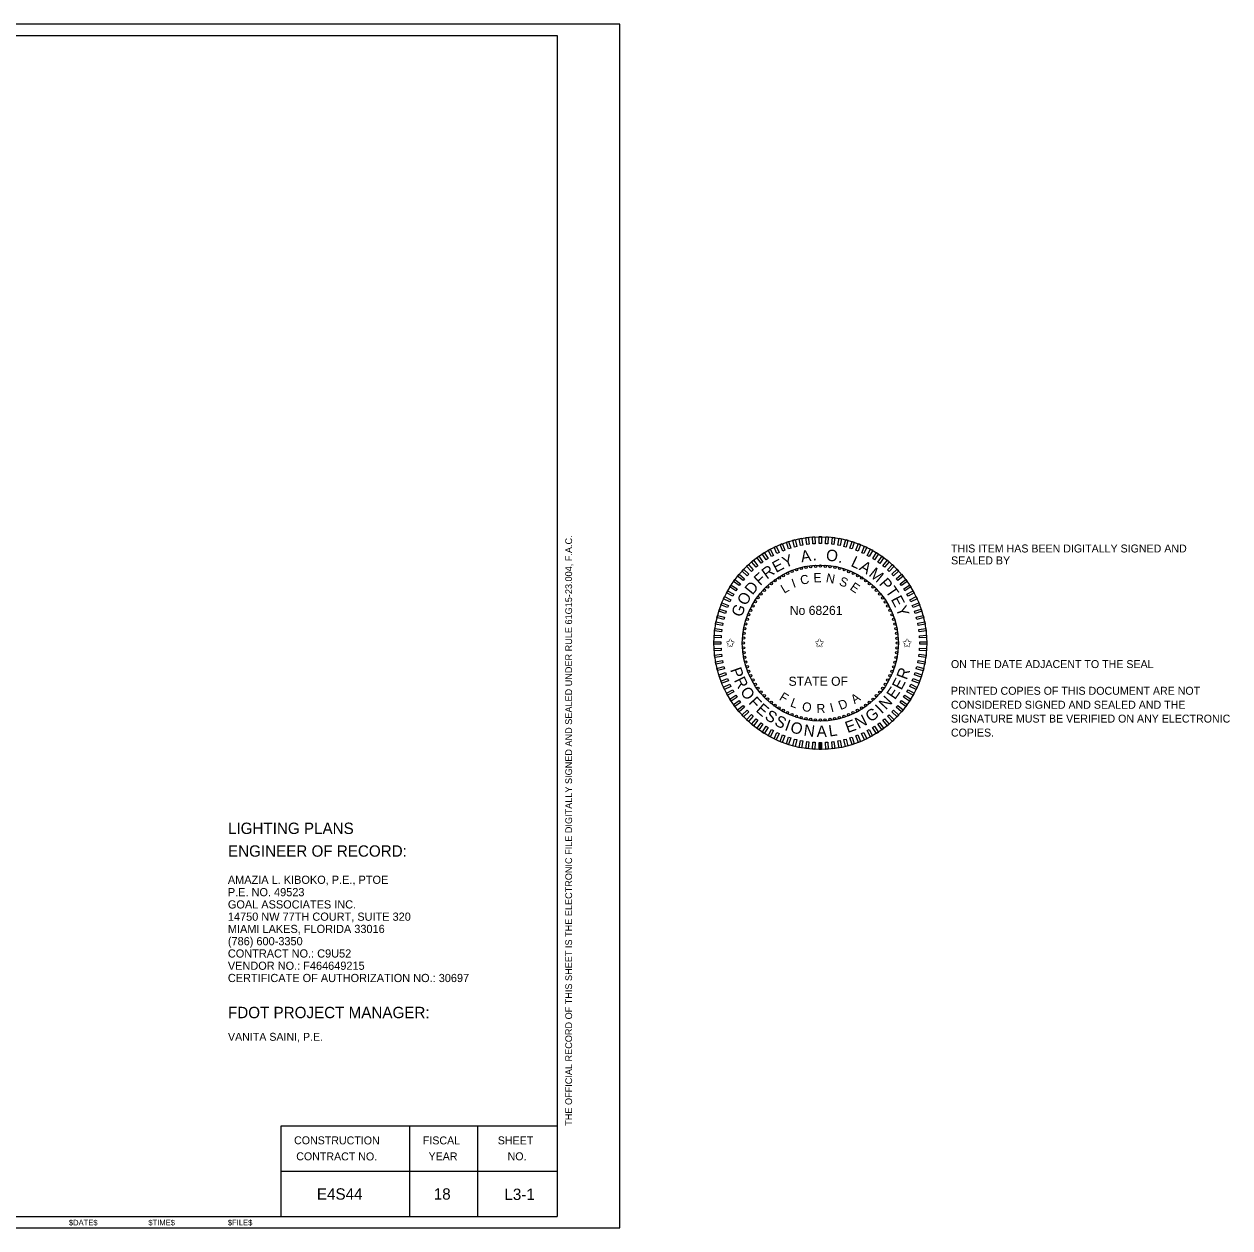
# Model space of a CAD drawing. Extents: x -820.2 to -798.4, y -2199.1 to -2188.5.
# Drawn here: x -808.97 to -798.35, y -2199.12 to -2188.52 of the extents above; entities that cross this region are included whole.
import ezdxf

# ---------------------------------------------------------------- set-up
doc = ezdxf.new("R2010")
doc.units = 0
for name, color, linetype in [('ActivePointCell_dp', 7, 'Continuous'), ('AdhocPoint_dp', 7, 'Continuous'), ('Logo_dp', 7, 'Continuous'), ('NonPlottingEle_dp', 7, 'Continuous'), ('PlotBorder_dp', 7, 'Continuous'), ('SheetBorder_dp', 7, 'Continuous'), ('SheetLines_dp', 7, 'Continuous'), ('TextLabel', 7, 'Continuous'), ('TextMinor', 7, 'Continuous'), ('TextMisc', 7, 'Continuous'), ('TextNotes', 7, 'Continuous'), ('TextShtNo', 7, 'Continuous')]:
    doc.layers.add(name, color=color, linetype=linetype)

msp = doc.modelspace()

# ---------------------------------------------------------------- linework, layer by layer
at = {"layer": 'ActivePointCell_dp'}
msp.add_line((-804.277, -2188.624), (-804.277, -2188.624), dxfattribs=at)
at = {"layer": 'AdhocPoint_dp'}
msp.add_line((-803.727, -2199.124), (-803.727, -2199.124), dxfattribs=at)
at = {"layer": 'Logo_dp'}
for p, q in [((-801.971, -2194.911), (-801.971, -2194.849)), ((-801.961, -2194.911), (-801.961, -2194.849)), ((-801.951, -2194.911), (-801.951, -2194.848))]:
    msp.add_line(p, q, dxfattribs=at)
for points in [[(-802.06, -2193.104), (-802.081, -2193.107), (-802.088, -2193.045), (-802.068, -2193.042)], [(-802.006, -2193.1), (-802.026, -2193.101), (-802.03, -2193.039), (-802.01, -2193.037)], [(-801.951, -2193.098), (-801.971, -2193.098), (-801.971, -2193.036), (-801.951, -2193.036)], [(-801.896, -2193.101), (-801.916, -2193.1), (-801.912, -2193.037), (-801.892, -2193.039)], [(-801.841, -2193.107), (-801.861, -2193.104), (-801.853, -2193.042), (-801.833, -2193.045)], [(-802.374, -2193.202), (-802.391, -2193.212), (-802.421, -2193.157), (-802.404, -2193.147)], [(-802.324, -2193.177), (-802.343, -2193.186), (-802.369, -2193.13), (-802.351, -2193.121)], [(-802.274, -2193.156), (-802.292, -2193.164), (-802.315, -2193.106), (-802.297, -2193.098)], [(-802.222, -2193.138), (-802.241, -2193.144), (-802.26, -2193.085), (-802.241, -2193.079)], [(-802.169, -2193.123), (-802.188, -2193.128), (-802.204, -2193.068), (-802.184, -2193.063)], [(-802.115, -2193.112), (-802.135, -2193.116), (-802.146, -2193.055), (-802.127, -2193.051)], [(-801.787, -2193.116), (-801.807, -2193.112), (-801.795, -2193.051), (-801.775, -2193.055)], [(-801.733, -2193.129), (-801.753, -2193.124), (-801.737, -2193.063), (-801.718, -2193.068)], [(-801.681, -2193.144), (-801.7, -2193.138), (-801.681, -2193.079), (-801.662, -2193.085)], [(-801.629, -2193.164), (-801.648, -2193.156), (-801.625, -2193.098), (-801.606, -2193.106)], [(-801.579, -2193.186), (-801.597, -2193.178), (-801.571, -2193.121), (-801.553, -2193.13)], [(-801.53, -2193.212), (-801.548, -2193.202), (-801.518, -2193.147), (-801.5, -2193.157)], [(-802.511, -2193.293), (-802.526, -2193.306), (-802.566, -2193.258), (-802.551, -2193.245)], [(-802.467, -2193.26), (-802.483, -2193.271), (-802.52, -2193.221), (-802.504, -2193.209)], [(-802.421, -2193.229), (-802.438, -2193.24), (-802.472, -2193.187), (-802.455, -2193.177)], [(-801.483, -2193.24), (-801.5, -2193.229), (-801.467, -2193.177), (-801.45, -2193.187)], [(-801.438, -2193.272), (-801.455, -2193.26), (-801.418, -2193.209), (-801.402, -2193.221)], [(-801.395, -2193.306), (-801.411, -2193.293), (-801.371, -2193.245), (-801.356, -2193.258)], [(-802.592, -2193.367), (-802.606, -2193.382), (-802.651, -2193.339), (-802.637, -2193.324)], [(-802.552, -2193.329), (-802.567, -2193.343), (-802.61, -2193.297), (-802.595, -2193.283)], [(-801.354, -2193.343), (-801.369, -2193.329), (-801.326, -2193.283), (-801.312, -2193.297)], [(-801.316, -2193.382), (-801.33, -2193.367), (-801.284, -2193.324), (-801.271, -2193.339)], [(-802.694, -2193.496), (-802.705, -2193.513), (-802.758, -2193.48), (-802.747, -2193.463)], [(-802.663, -2193.451), (-802.675, -2193.467), (-802.725, -2193.431), (-802.713, -2193.414)], [(-802.629, -2193.408), (-802.642, -2193.423), (-802.69, -2193.384), (-802.677, -2193.368)], [(-801.28, -2193.424), (-801.293, -2193.408), (-801.245, -2193.368), (-801.232, -2193.384)], [(-801.247, -2193.467), (-801.259, -2193.451), (-801.208, -2193.414), (-801.197, -2193.431)], [(-801.217, -2193.513), (-801.227, -2193.496), (-801.175, -2193.463), (-801.164, -2193.48)], [(-802.748, -2193.592), (-802.757, -2193.61), (-802.813, -2193.583), (-802.805, -2193.565)], [(-802.723, -2193.543), (-802.733, -2193.561), (-802.787, -2193.531), (-802.778, -2193.513)], [(-801.189, -2193.561), (-801.199, -2193.543), (-801.144, -2193.513), (-801.135, -2193.531)], [(-801.165, -2193.61), (-801.173, -2193.592), (-801.117, -2193.565), (-801.108, -2193.584)], [(-802.79, -2193.693), (-802.796, -2193.713), (-802.856, -2193.693), (-802.849, -2193.674)], [(-802.771, -2193.642), (-802.778, -2193.661), (-802.836, -2193.638), (-802.829, -2193.619)], [(-801.144, -2193.661), (-801.151, -2193.642), (-801.093, -2193.619), (-801.086, -2193.638)], [(-801.126, -2193.713), (-801.132, -2193.694), (-801.072, -2193.674), (-801.066, -2193.694)], [(-802.806, -2193.746), (-802.811, -2193.766), (-802.871, -2193.75), (-802.866, -2193.731)], [(-801.111, -2193.766), (-801.116, -2193.746), (-801.055, -2193.731), (-801.05, -2193.75)], [(-802.828, -2193.854), (-802.83, -2193.874), (-802.892, -2193.866), (-802.89, -2193.846)], [(-802.819, -2193.8), (-802.822, -2193.819), (-802.884, -2193.808), (-802.88, -2193.788)], [(-801.099, -2193.82), (-801.103, -2193.8), (-801.042, -2193.788), (-801.038, -2193.808)], [(-801.092, -2193.874), (-801.094, -2193.854), (-801.032, -2193.846), (-801.03, -2193.866)], [(-802.836, -2193.963), (-802.836, -2193.984), (-802.898, -2193.984), (-802.898, -2193.963)], [(-802.834, -2193.908), (-802.835, -2193.929), (-802.897, -2193.925), (-802.896, -2193.904)], [(-801.087, -2193.929), (-801.088, -2193.909), (-801.026, -2193.905), (-801.025, -2193.925)], [(-801.086, -2193.984), (-801.086, -2193.964), (-801.023, -2193.964), (-801.023, -2193.984)], [(-802.835, -2194.018), (-802.834, -2194.038), (-802.896, -2194.042), (-802.897, -2194.022)], [(-802.83, -2194.073), (-802.828, -2194.093), (-802.89, -2194.101), (-802.892, -2194.081)], [(-801.094, -2194.093), (-801.092, -2194.073), (-801.03, -2194.081), (-801.032, -2194.101)], [(-801.088, -2194.039), (-801.087, -2194.018), (-801.025, -2194.022), (-801.026, -2194.043)], [(-802.822, -2194.127), (-802.819, -2194.147), (-802.88, -2194.159), (-802.884, -2194.139)], [(-802.811, -2194.181), (-802.806, -2194.201), (-802.866, -2194.216), (-802.871, -2194.197)], [(-801.116, -2194.201), (-801.111, -2194.181), (-801.05, -2194.197), (-801.055, -2194.217)], [(-801.103, -2194.147), (-801.1, -2194.128), (-801.038, -2194.139), (-801.042, -2194.159)], [(-802.796, -2194.234), (-802.79, -2194.253), (-802.849, -2194.273), (-802.856, -2194.254)], [(-802.778, -2194.286), (-802.771, -2194.305), (-802.829, -2194.328), (-802.836, -2194.309)], [(-801.151, -2194.305), (-801.144, -2194.286), (-801.086, -2194.309), (-801.093, -2194.328)], [(-801.132, -2194.254), (-801.126, -2194.234), (-801.066, -2194.254), (-801.072, -2194.273)], [(-802.757, -2194.337), (-802.748, -2194.355), (-802.805, -2194.382), (-802.814, -2194.363)], [(-802.733, -2194.386), (-802.723, -2194.404), (-802.778, -2194.434), (-802.787, -2194.416)], [(-801.199, -2194.404), (-801.189, -2194.386), (-801.135, -2194.416), (-801.144, -2194.434)], [(-801.174, -2194.355), (-801.165, -2194.337), (-801.108, -2194.364), (-801.117, -2194.382)], [(-802.705, -2194.434), (-802.694, -2194.451), (-802.747, -2194.484), (-802.758, -2194.467)], [(-802.675, -2194.48), (-802.663, -2194.496), (-802.713, -2194.533), (-802.725, -2194.516)], [(-802.642, -2194.523), (-802.629, -2194.539), (-802.677, -2194.579), (-802.69, -2194.563)], [(-801.293, -2194.539), (-801.28, -2194.524), (-801.232, -2194.563), (-801.245, -2194.579)], [(-801.259, -2194.496), (-801.247, -2194.48), (-801.197, -2194.516), (-801.208, -2194.533)], [(-801.228, -2194.451), (-801.217, -2194.434), (-801.164, -2194.467), (-801.175, -2194.484)], [(-802.606, -2194.565), (-802.592, -2194.58), (-802.637, -2194.623), (-802.651, -2194.608)], [(-802.567, -2194.604), (-802.553, -2194.618), (-802.595, -2194.664), (-802.61, -2194.65)], [(-801.369, -2194.618), (-801.355, -2194.605), (-801.312, -2194.65), (-801.327, -2194.664)], [(-801.33, -2194.58), (-801.316, -2194.565), (-801.271, -2194.608), (-801.285, -2194.623)], [(-802.527, -2194.641), (-802.511, -2194.654), (-802.551, -2194.702), (-802.566, -2194.689)], [(-802.483, -2194.675), (-802.467, -2194.687), (-802.504, -2194.738), (-802.52, -2194.726)], [(-802.438, -2194.707), (-802.421, -2194.718), (-802.455, -2194.77), (-802.472, -2194.76)], [(-802.391, -2194.735), (-802.374, -2194.745), (-802.404, -2194.8), (-802.421, -2194.79)], [(-801.548, -2194.745), (-801.531, -2194.736), (-801.501, -2194.79), (-801.518, -2194.8)], [(-801.501, -2194.718), (-801.484, -2194.707), (-801.45, -2194.76), (-801.467, -2194.771)], [(-801.455, -2194.687), (-801.439, -2194.676), (-801.402, -2194.726), (-801.418, -2194.738)], [(-801.411, -2194.654), (-801.395, -2194.641), (-801.356, -2194.689), (-801.371, -2194.702)], [(-802.343, -2194.761), (-802.324, -2194.77), (-802.351, -2194.826), (-802.369, -2194.817)], [(-802.293, -2194.783), (-802.274, -2194.791), (-802.297, -2194.849), (-802.315, -2194.841)], [(-802.241, -2194.803), (-802.222, -2194.809), (-802.241, -2194.868), (-802.26, -2194.862)], [(-802.188, -2194.819), (-802.169, -2194.824), (-802.184, -2194.884), (-802.204, -2194.879)], [(-802.135, -2194.831), (-802.115, -2194.835), (-802.127, -2194.896), (-802.147, -2194.892)], [(-802.081, -2194.84), (-802.061, -2194.843), (-802.068, -2194.905), (-802.089, -2194.902)], [(-802.026, -2194.846), (-802.006, -2194.847), (-802.01, -2194.91), (-802.03, -2194.909)], [(-801.916, -2194.847), (-801.896, -2194.846), (-801.892, -2194.909), (-801.912, -2194.91)], [(-801.861, -2194.843), (-801.841, -2194.84), (-801.834, -2194.902), (-801.854, -2194.905)], [(-801.807, -2194.835), (-801.787, -2194.831), (-801.775, -2194.893), (-801.795, -2194.896)], [(-801.753, -2194.824), (-801.734, -2194.819), (-801.718, -2194.879), (-801.738, -2194.884)], [(-801.7, -2194.809), (-801.681, -2194.803), (-801.662, -2194.862), (-801.681, -2194.868)], [(-801.648, -2194.791), (-801.63, -2194.783), (-801.607, -2194.841), (-801.625, -2194.849)], [(-801.598, -2194.77), (-801.579, -2194.761), (-801.553, -2194.818), (-801.571, -2194.826)], [(-801.971, -2194.849), (-801.951, -2194.849), (-801.951, -2194.911), (-801.971, -2194.911)]]:
    msp.add_lwpolyline(points, close=True, dxfattribs=at)
for centre in [(-802.249, -2193.36), (-802.21, -2193.343), (-802.17, -2193.329), (-802.129, -2193.317), (-802.087, -2193.308), (-802.045, -2193.301), (-802.003, -2193.297), (-801.96, -2193.296), (-801.918, -2193.297), (-801.875, -2193.301), (-801.833, -2193.308), (-801.792, -2193.317), (-801.751, -2193.329), (-801.711, -2193.344), (-801.672, -2193.361), (-802.392, -2193.451), (-802.359, -2193.425), (-802.323, -2193.401), (-802.287, -2193.38), (-801.634, -2193.38), (-801.597, -2193.402), (-801.562, -2193.426), (-801.529, -2193.452), (-802.509, -2193.575), (-802.483, -2193.541), (-802.454, -2193.509), (-802.424, -2193.479), (-801.497, -2193.48), (-801.467, -2193.51), (-801.439, -2193.542), (-801.413, -2193.576), (-802.574, -2193.685), (-802.554, -2193.647), (-802.533, -2193.61), (-801.389, -2193.611), (-801.367, -2193.648), (-801.348, -2193.686), (-802.605, -2193.764), (-802.591, -2193.724), (-801.331, -2193.725), (-801.316, -2193.765), (-802.633, -2193.888), (-802.626, -2193.846), (-802.617, -2193.805), (-801.305, -2193.806), (-801.295, -2193.847), (-801.289, -2193.889), (-802.638, -2193.973), (-802.637, -2193.93), (-801.285, -2193.932), (-801.283, -2193.974), (-802.637, -2194.016), (-802.633, -2194.058), (-802.626, -2194.1), (-801.296, -2194.101), (-801.289, -2194.059), (-801.285, -2194.017), (-802.617, -2194.141), (-802.605, -2194.182), (-801.317, -2194.183), (-801.305, -2194.143), (-802.591, -2194.222), (-802.574, -2194.261), (-802.555, -2194.299), (-801.368, -2194.3), (-801.348, -2194.262), (-801.331, -2194.223), (-802.533, -2194.336), (-802.509, -2194.371), (-802.483, -2194.405), (-801.439, -2194.406), (-801.413, -2194.372), (-801.389, -2194.337), (-802.455, -2194.437), (-802.425, -2194.467), (-802.393, -2194.495), (-802.36, -2194.521), (-801.563, -2194.522), (-801.53, -2194.496), (-801.498, -2194.468), (-801.467, -2194.438), (-802.324, -2194.545), (-802.288, -2194.567), (-802.25, -2194.586), (-802.211, -2194.603), (-802.171, -2194.618), (-802.13, -2194.63), (-802.088, -2194.639), (-802.046, -2194.646), (-801.877, -2194.646), (-801.835, -2194.639), (-801.793, -2194.63), (-801.752, -2194.618), (-801.712, -2194.604), (-801.673, -2194.587), (-801.635, -2194.567), (-801.598, -2194.546), (-802.004, -2194.65), (-801.961, -2194.651), (-801.919, -2194.65)]:
    msp.add_circle(centre, 0.01, dxfattribs=at)
at = {"layer": 'NonPlottingEle_dp'}
for radius in [0.937, 0.687]:
    msp.add_circle((-801.961, -2193.974), radius, dxfattribs=at)
at = {"layer": 'PlotBorder_dp'}
msp.add_lwpolyline([(-820.227, -2199.124), (-803.727, -2199.124), (-803.727, -2188.524), (-820.227, -2188.524)], close=True, dxfattribs=at)
at = {"layer": 'SheetBorder_dp'}
for p, q in [((-819.677, -2188.624), (-804.277, -2188.624)), ((-804.277, -2188.624), (-804.277, -2199.024)), ((-819.677, -2199.024), (-804.277, -2199.024))]:
    msp.add_line(p, q, dxfattribs=at)
at = {"layer": 'SheetLines_dp'}
for p, q in [((-806.708, -2198.224), (-804.277, -2198.224)), ((-806.708, -2199.024), (-806.708, -2198.224)), ((-805.577, -2199.024), (-805.577, -2198.224)), ((-804.977, -2199.024), (-804.977, -2198.224)), ((-806.708, -2198.624), (-804.277, -2198.624))]:
    msp.add_line(p, q, dxfattribs=at)

# ---------------------------------------------------------------- texts
at = {"layer": 'Logo_dp'}
for s, height, rotation, p in [('O', 0.1, 352.1877, (-801.916, -2193.245)), ('E', 0.1, 28.1055, (-802.351, -2193.357)), ('Y', 0.1, 21.0633, (-802.273, -2193.314)), ('A', 0.1, 8.8088, (-802.126, -2193.263)), ('.', 0.1, 1.0418, (-802.028, -2193.247)), ('.', 0.1, 343.5268, (-801.807, -2193.261)), ('L', 0.1, 334.6727, (-801.699, -2193.293)), ('F', 0.1, 42.3772, (-802.491, -2193.473)), ('R', 0.1, 35.9269, (-802.432, -2193.416)), ('E', 0.08, 0.4186, (-802.021, -2193.438)), ('N', 0.08, 349.2914, (-801.916, -2193.437)), ('A', 0.1, 328.4096, (-801.626, -2193.325)), ('M', 0.1, 320.6426, (-801.541, -2193.377)), ('D', 0.1, 50.8569, (-802.559, -2193.556)), ('L', 0.08, 30.4021, (-802.28, -2193.54)), ('I', 0.08, 20.0117, (-802.197, -2193.489)), ('C', 0.08, 12.2025, (-802.129, -2193.462)), ('S', 0.08, 337.0221, (-801.803, -2193.459)), ('E', 0.08, 325.8663, (-801.707, -2193.499)), ('P', 0.1, 311.1966, (-801.449, -2193.454)), ('T', 0.1, 304.4563, (-801.392, -2193.517)), ('O', 0.1, 59.5178, (-802.615, -2193.651)), ('E', 0.1, 297.6315, (-801.342, -2193.588)), ('G', 0.1, 68.0518, (-802.656, -2193.752)), ('Y', 0.1, 290.5893, (-801.299, -2193.667)), ('P', 0.1, 289.4055, (-802.756, -2194.208)), ('R', 0.1, 69.5134, (-801.201, -2194.303)), ('R', 0.1, 296.1458, (-802.723, -2194.3)), ('E', 0.1, 62.4712, (-801.247, -2194.394)), ('O', 0.1, 303.9671, (-802.671, -2194.4)), ('F', 0.08, 328.7241, (-802.329, -2194.47)), ('A', 0.08, 34.4992, (-801.659, -2194.513)), ('E', 0.1, 55.4289, (-801.304, -2194.478)), ('F', 0.1, 312.628, (-802.599, -2194.502)), ('E', 0.1, 319.0783, (-802.535, -2194.571)), ('L', 0.08, 339.2916, (-802.232, -2194.529)), ('O', 0.08, 349.6821, (-802.127, -2194.569)), ('R', 0.08, 2.3398, (-801.993, -2194.591)), ('I', 0.08, 14.2037, (-801.865, -2194.584)), ('D', 0.08, 22.0128, (-801.783, -2194.565)), ('I', 0.1, 43.6456, (-801.421, -2194.602)), ('N', 0.1, 47.1788, (-801.383, -2194.567)), ('S', 0.1, 326.1206, (-802.458, -2194.637)), ('S', 0.1, 333.193, (-802.372, -2194.693)), ('N', 0.1, 26.8614, (-801.625, -2194.731)), ('G', 0.1, 35.1115, (-801.52, -2194.675)), ('I', 0.1, 340.2654, (-802.281, -2194.738)), ('O', 0.1, 343.7986, (-802.233, -2194.756)), ('N', 0.1, 352.4595, (-802.112, -2194.788)), ('A', 0.1, 0.7097, (-801.993, -2194.801)), ('L', 0.1, 8.4767, (-801.881, -2194.798)), ('E', 0.1, 19.8191, (-801.721, -2194.767))]:
    msp.add_text(s, height=height, rotation=rotation, dxfattribs=at).set_placement(p)
for s, p in [('No 68261', (-802.23, -2193.726)), ('✩', (-802.796, -2194.011)), ('✩', (-802.011, -2194.011)), ('✩', (-801.239, -2194.011)), ('STATE OF', (-802.241, -2194.35))]:
    msp.add_text(s, height=0.08, dxfattribs=at).set_placement(p)
at = {"layer": 'TextLabel'}
for s, height, p in [('LIGHTING PLANS', 0.1, (-807.177, -2195.655)), ('ENGINEER OF RECORD:', 0.1, (-807.177, -2195.855)), ('AMAZIA L. KIBOKO, P.E., PTOE', 0.07202, (-807.178, -2196.094)), ('P.E. NO. 49523', 0.07202, (-807.178, -2196.203)), ('GOAL ASSOCIATES INC. ', 0.07202, (-807.178, -2196.311)), ('14750 NW 77TH COURT, SUITE 320', 0.07202, (-807.178, -2196.419)), ('MIAMI LAKES, FLORIDA 33016', 0.07202, (-807.178, -2196.527)), ('(786) 600-3350', 0.07202, (-807.178, -2196.635)), ('CONTRACT NO.: C9U52', 0.07202, (-807.178, -2196.743)), ('VENDOR NO.: F464649215', 0.07202, (-807.178, -2196.851)), ('CERTIFICATE OF AUTHORIZATION NO.: 30697', 0.07202, (-807.178, -2196.959)), ('E4S44', 0.1, (-806.394, -2198.875)), ('18', 0.1, (-805.365, -2198.875))]:
    msp.add_text(s, height=height, dxfattribs=at).set_placement(p)
at = {"layer": 'TextMinor'}
for s, p in [('$DATE$', (-808.578, -2199.102)), ('$TIME$', (-807.878, -2199.102)), ('$FILE$', (-807.178, -2199.102))]:
    msp.add_text(s, height=0.05, rotation=360, dxfattribs=at).set_placement(p)
at = {"layer": 'TextMisc'}
msp.add_text('THE OFFICIAL RECORD OF THIS SHEET IS THE ELECTRONIC FILE DIGITALLY SIGNED AND SEALED UNDER RULE 61G15-23.004, F.A.C.', height=0.06, rotation=90, dxfattribs=at).set_placement((-804.147, -2198.224))
for s, p in [('THIS ITEM HAS BEEN DIGITALLY SIGNED AND ', (-800.81, -2193.176)), ('SEALED BY', (-800.81, -2193.281)), ('ON THE DATE ADJACENT TO THE SEAL', (-800.811, -2194.194)), ('PRINTED COPIES OF THIS DOCUMENT ARE NOT ', (-800.811, -2194.429)), ('CONSIDERED SIGNED AND SEALED AND THE ', (-800.811, -2194.552)), ('SIGNATURE MUST BE VERIFIED ON ANY ELECTRONIC ', (-800.811, -2194.674)), ('COPIES.', (-800.811, -2194.797))]:
    msp.add_text(s, height=0.07, dxfattribs=at).set_placement(p)
at = {"layer": 'TextNotes'}
for s, height, p in [('FDOT PROJECT MANAGER:', 0.1, (-807.177, -2197.277)), ('VANITA SAINI, P.E.', 0.07, (-807.177, -2197.476))]:
    msp.add_text(s, height=height, dxfattribs=at).set_placement(p)
for s, p in [('CONSTRUCTION', (-806.595, -2198.387)), ('FISCAL', (-805.461, -2198.388)), ('SHEET', (-804.801, -2198.388)), ('CONTRACT NO.', (-806.576, -2198.528)), ('YEAR', (-805.411, -2198.528)), ('NO.', (-804.715, -2198.528))]:
    msp.add_text(s, height=0.07, rotation=359.8607, dxfattribs=at).set_placement(p)
at = {"layer": 'TextShtNo'}
msp.add_text('L3-1', height=0.1, dxfattribs=at).set_placement((-804.743, -2198.878))

doc.saveas('drawing.dxf')
